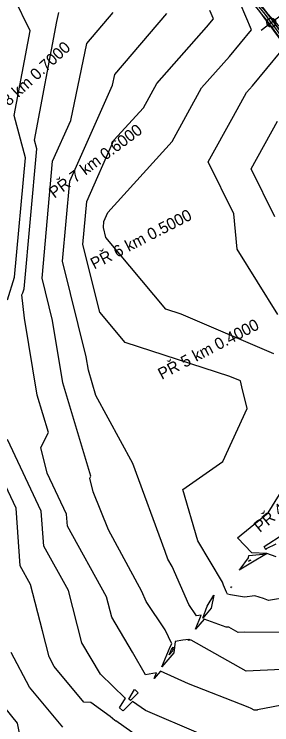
# Model space of a CAD drawing. Extents: x -549394 to -546608, y -1037055 to -1033629.
# Drawn here: x -548203 to -548001, y -1034976 to -1034420 of the extents above; entities that cross this region are included whole.
import ezdxf

# ---------------------------------------------------------------- set-up
doc = ezdxf.new("R2010")
doc.units = 0
for name, color, linetype in [('hlavni_vrst', 7, 'Continuous'), ('norm_vrst', 7, 'Continuous'), ('u_sirka_1_5m', 7, 'Continuous'), ('x_navrh_C21', 7, 'Continuous'), ('x_osa_C21', 7, 'Continuous'), ('x_popis_pricne_rezy_C21', 7, 'Continuous'), ('x_popis_velky_C21', 7, 'Continuous')]:
    doc.layers.add(name, color=color, linetype=linetype)

msp = doc.modelspace()

# ---------------------------------------------------------------- linework, layer by layer
at = {"layer": 'hlavni_vrst'}
for p, q in [((-548146.08, -1034442.45), (-548125.53, -1034418.32)), ((-548158.61, -1034502.63), (-548146.08, -1034442.45)), ((-548172.84, -1034534.63), (-548158.61, -1034502.63)), ((-548017.39, -1034540.43), (-547996.78, -1034503.15)), ((-548181.01, -1034626.04), (-548172.84, -1034534.63)), ((-547998.99, -1034578.18), (-548017.39, -1034540.43)), ((-548172.85, -1034659.09), (-548181.01, -1034626.04)), ((-548164.9, -1034707.86), (-548172.85, -1034659.09)), ((-548142.85, -1034780.89), (-548164.9, -1034707.86)), ((-548143.73, -1034782.59), (-548142.85, -1034780.89)), ((-548140.96, -1034793.3), (-548143.73, -1034782.59)), ((-548129.19, -1034823), (-548140.96, -1034793.3)), ((-548102.99, -1034871.31), (-548129.19, -1034823)), ((-548099.52, -1034879.12), (-548102.99, -1034871.31)), ((-548084.87, -1034901.12), (-548099.52, -1034879.12)), ((-548079.44, -1034912.17), (-548084.87, -1034901.12)), ((-548076.88, -1034910.42), (-548077.94, -1034919.17)), ((-548071.04, -1034909.31), (-548076.88, -1034910.42)), ((-548066.15, -1034908.68), (-548071.04, -1034909.31)), ((-548066.47, -1034909.49), (-548066.15, -1034908.68)), ((-548065.96, -1034908.91), (-548066.47, -1034909.49)), ((-548064.69, -1034909.38), (-548065.96, -1034908.91)), ((-548064.55, -1034909.36), (-548064.69, -1034909.38)), ((-548021.3, -1034933.65), (-548064.55, -1034909.36)), ((-548087.44, -1034930.05), (-548080.86, -1034914.52)), ((-548080.86, -1034914.52), (-548079.44, -1034912.17)), ((-548077.94, -1034919.17), (-548087.44, -1034930.05)), ((-547993.65, -1034932.39), (-548021.3, -1034933.65)), ((-548200.15, -1034974.14), (-548210.1, -1034962.11)), ((-548198.58, -1034982.16), (-548200.15, -1034974.14))]:
    msp.add_line(p, q, dxfattribs=at)
at = {"layer": 'norm_vrst'}
for p, q in [((-548190.3, -1034432.56), (-548227.23, -1034357.2)), ((-548017.25, -1034431.88), (-548026.05, -1034410.86)), ((-548047.04, -1034423.24), (-548049.77, -1034416.71)), ((-548169.38, -1034425.17), (-548167.91, -1034418.13)), ((-548124.25, -1034466.77), (-548083.54, -1034418.98)), ((-548186.88, -1034518.02), (-548169.38, -1034425.17)), ((-548052.38, -1034429.67), (-548047.04, -1034423.24)), ((-548202.78, -1034498.76), (-548190.3, -1034432.56)), ((-548091.3, -1034473.64), (-548052.38, -1034429.67)), ((-548034.46, -1034452.59), (-548017.25, -1034431.88)), ((-548016.54, -1034475.52), (-547994.11, -1034448.52)), ((-548056.24, -1034477.2), (-548034.46, -1034452.59)), ((-548125.98, -1034475.07), (-548124.25, -1034466.77)), ((-548159.45, -1034550.3), (-548125.98, -1034475.07)), ((-548101.78, -1034492.75), (-548091.3, -1034473.64)), ((-548079.18, -1034519.05), (-548056.24, -1034477.2)), ((-548021.17, -1034480.75), (-548016.54, -1034475.52)), ((-548031.4, -1034499.41), (-548021.17, -1034480.75)), ((-548124.79, -1034518.16), (-548101.78, -1034492.75)), ((-548193.98, -1034532.04), (-548202.78, -1034498.76)), ((-548051.05, -1034534.94), (-548031.4, -1034499.41)), ((-548185.07, -1034524.89), (-548186.88, -1034518.02)), ((-548146.06, -1034565.97), (-548124.79, -1034518.16)), ((-548129.58, -1034574.7), (-548079.18, -1034519.05)), ((-548195.18, -1034634.51), (-548185.07, -1034524.89)), ((-548202.58, -1034625.32), (-548193.98, -1034532.04)), ((-548031.16, -1034575.74), (-548051.05, -1034534.94)), ((-548165.04, -1034612.88), (-548159.45, -1034550.3)), ((-548149.08, -1034599.71), (-548146.06, -1034565.97)), ((-548132.68, -1034581.65), (-548129.58, -1034574.7)), ((-548028.57, -1034603.4), (-548031.16, -1034575.74)), ((-548133.11, -1034586.55), (-548132.68, -1034581.65)), ((-548131.21, -1034594.26), (-548133.11, -1034586.55)), ((-548084.19, -1034650.32), (-548131.21, -1034594.26)), ((-548135.97, -1034652.77), (-548149.08, -1034599.71)), ((-547996.51, -1034654.45), (-548028.57, -1034603.4)), ((-548146.55, -1034687.75), (-548165.04, -1034612.88)), ((-548208.07, -1034642.95), (-548202.58, -1034625.32)), ((-548196.89, -1034639.11), (-548196.13, -1034637.57)), ((-548194.75, -1034657.36), (-548196.89, -1034639.11)), ((-548196.13, -1034637.57), (-548195.18, -1034634.51)), ((-548072.27, -1034654.17), (-548084.19, -1034650.32)), ((-548116.13, -1034676.43), (-548135.97, -1034652.77)), ((-547999.8, -1034685.36), (-548072.27, -1034654.17)), ((-548184.93, -1034717.6), (-548194.75, -1034657.36)), ((-548034.09, -1034702.92), (-548116.13, -1034676.43)), ((-548144.86, -1034698.12), (-548146.55, -1034687.75)), ((-548138.9, -1034717.87), (-548144.86, -1034698.12)), ((-548025.76, -1034706.51), (-548034.09, -1034702.92)), ((-548024.71, -1034711.2), (-548025.76, -1034706.51)), ((-548020.75, -1034727.95), (-548024.71, -1034711.2)), ((-548176.09, -1034746.9), (-548184.93, -1034717.6)), ((-548109.97, -1034770.99), (-548138.9, -1034717.87)), ((-548039.64, -1034769.5), (-548020.75, -1034727.95)), ((-548182.14, -1034758.61), (-548176.09, -1034746.9)), ((-548181.64, -1034808.42), (-548207.99, -1034752.34)), ((-548176.94, -1034778.68), (-548182.14, -1034758.61)), ((-548201.42, -1034806.04), (-548221.28, -1034763.77)), ((-548084.86, -1034840.06), (-548109.97, -1034770.99)), ((-548070.96, -1034791.48), (-548039.64, -1034769.5)), ((-548161.86, -1034810.79), (-548176.94, -1034778.68)), ((-548059.11, -1034831.52), (-548070.96, -1034791.48)), ((-548004.18, -1034809.72), (-547995.42, -1034795.27)), ((-548198.21, -1034851.18), (-548201.42, -1034806.04)), ((-548179.7, -1034835.65), (-548181.64, -1034808.42)), ((-548161.19, -1034820.11), (-548161.86, -1034810.79)), ((-548028.31, -1034829.28), (-548004.18, -1034809.72)), ((-548130.56, -1034875.29), (-548161.19, -1034820.11)), ((-548007.41, -1034835.99), (-547991.97, -1034826.01)), ((-548039.89, -1034863.86), (-548059.11, -1034831.52)), ((-548016.86, -1034840.89), (-548028.31, -1034829.28)), ((-548160.33, -1034870.54), (-548179.7, -1034835.65)), ((-548006, -1034838.59), (-548007.41, -1034835.99)), ((-548005.82, -1034837.88), (-548006, -1034838.59)), ((-547998.17, -1034834.14), (-548005.82, -1034837.88)), ((-548082.56, -1034845.87), (-548084.86, -1034840.06)), ((-548026.18, -1034853.86), (-548019.45, -1034844.98)), ((-548019.45, -1034844.98), (-548019.3, -1034843.12)), ((-548019.3, -1034843.12), (-548005.47, -1034841.82)), ((-548005.47, -1034841.82), (-548017.71, -1034849.03)), ((-548005.35, -1034841.47), (-548016.86, -1034840.89)), ((-548005.25, -1034841.66), (-548005.35, -1034841.47)), ((-548005.18, -1034841.41), (-548005.25, -1034841.66)), ((-547997.95, -1034844.08), (-548005.18, -1034841.41)), ((-548079.34, -1034851.8), (-548082.56, -1034845.87)), ((-548017.71, -1034849.03), (-548026.84, -1034854.66)), ((-548018.72, -1034847.22), (-548019.47, -1034847.69)), ((-548019.47, -1034847.69), (-548019.42, -1034847.62)), ((-548019.42, -1034847.62), (-548018.86, -1034846.89)), ((-548018.86, -1034846.89), (-548018.85, -1034846.73)), ((-548018.85, -1034846.73), (-548017.71, -1034846.63)), ((-548017.71, -1034846.63), (-548018.72, -1034847.22)), ((-548190.1, -1034865.79), (-548198.21, -1034851.18)), ((-548066.23, -1034881.33), (-548079.34, -1034851.8)), ((-548026.84, -1034854.66), (-548026.18, -1034853.86)), ((-548180.76, -1034902.12), (-548190.1, -1034865.79)), ((-548039.04, -1034866.27), (-548039.89, -1034863.86)), ((-548036.77, -1034871.74), (-548039.04, -1034866.27)), ((-548149.83, -1034911.36), (-548160.33, -1034870.54)), ((-548035.91, -1034873.34), (-548036.77, -1034871.74)), ((-548032.99, -1034867.74), (-548033.28, -1034867.88)), ((-548033.28, -1034867.88), (-548033.22, -1034867.96)), ((-548033.27, -1034868.41), (-548032.89, -1034867.65)), ((-548033.22, -1034867.96), (-548033.27, -1034868.41)), ((-548032.89, -1034867.65), (-548032.99, -1034867.74)), ((-548126.46, -1034891.22), (-548130.56, -1034875.29)), ((-548051.83, -1034882.77), (-548046.58, -1034874.17)), ((-548046.58, -1034874.17), (-548048.77, -1034884.33)), ((-548033.72, -1034873.9), (-548035.91, -1034873.34)), ((-548022.71, -1034875.76), (-548033.72, -1034873.9)), ((-548014.61, -1034874.54), (-548022.71, -1034875.76)), ((-548007.97, -1034876.79), (-548014.61, -1034874.54)), ((-548003.88, -1034878.17), (-548007.97, -1034876.79)), ((-547982.46, -1034874.58), (-548003.88, -1034878.17)), ((-548060.3, -1034890.23), (-548066.23, -1034881.33)), ((-548055.4, -1034892.04), (-548051.83, -1034882.77)), ((-548048.77, -1034884.33), (-548055.4, -1034892.04)), ((-548110.29, -1034918.6), (-548126.46, -1034891.22)), ((-548060.93, -1034900.77), (-548056.69, -1034889.77)), ((-548054.13, -1034892.86), (-548060.93, -1034900.77)), ((-548056.69, -1034889.77), (-548060.3, -1034890.23)), ((-548036.92, -1034899.22), (-548054.13, -1034892.86)), ((-548035.07, -1034899.04), (-548036.92, -1034899.22)), ((-548027.56, -1034903.25), (-548035.07, -1034899.04)), ((-548175.6, -1034922.33), (-548180.76, -1034902.12)), ((-548022.77, -1034903.03), (-548027.56, -1034903.25)), ((-547988.35, -1034903.27), (-548022.77, -1034903.03)), ((-548135.34, -1034935.88), (-548149.83, -1034911.36)), ((-548081.56, -1034920.82), (-548079.78, -1034916.62)), ((-548079.78, -1034916.62), (-548078.6, -1034914.67)), ((-548078.6, -1034914.67), (-548078.99, -1034917.88)), ((-548190.85, -1034946.02), (-548205.16, -1034918.95)), ((-548171.59, -1034929.93), (-548175.6, -1034922.33)), ((-548100.2, -1034936.38), (-548110.29, -1034918.6)), ((-548078.99, -1034917.88), (-548081.56, -1034920.82)), ((-548148.41, -1034957.93), (-548171.59, -1034929.93)), ((-548088.41, -1034933.65), (-548093.32, -1034939.28)), ((-548066.5, -1034943.54), (-548088.41, -1034933.65)), ((-548115.98, -1034954.78), (-548135.34, -1034935.88)), ((-548091.42, -1034934.79), (-548100.2, -1034936.38)), ((-548093.32, -1034939.28), (-548091.42, -1034934.79)), ((-548019.86, -1034961.81), (-548066.5, -1034943.54)), ((-548164.85, -1034977.44), (-548190.85, -1034946.02)), ((-548113.27, -1034955.43), (-548108.63, -1034947.86)), ((-548105.77, -1034950.4), (-548112, -1034956.5)), ((-548108.63, -1034947.86), (-548108.21, -1034948.2)), ((-548108.21, -1034948.2), (-548105.77, -1034950.4)), ((-548120.5, -1034962.22), (-548115.91, -1034954.73)), ((-548115.91, -1034954.73), (-548115.98, -1034954.78)), ((-548112.22, -1034956.37), (-548113.27, -1034955.43)), ((-547970.95, -1034956.03), (-548012.58, -1034963.69)), ((-548142.91, -1034958.09), (-548148.41, -1034957.93)), ((-548127.88, -1034969.1), (-548142.91, -1034958.09)), ((-548110.32, -1034957.28), (-548117.74, -1034964.56)), ((-548112, -1034956.5), (-548112.22, -1034956.37)), ((-548100.16, -1034964.38), (-548110.32, -1034957.28)), ((-548017.41, -1034962.72), (-548019.86, -1034961.81)), ((-548118.22, -1034964.27), (-548120.5, -1034962.22)), ((-548117.74, -1034964.56), (-548118.22, -1034964.27)), ((-548058.63, -1034981.96), (-548100.16, -1034964.38)), ((-548015.03, -1034964.05), (-548017.41, -1034962.72)), ((-548012.91, -1034963.95), (-548015.03, -1034964.05)), ((-548012.58, -1034963.69), (-548012.91, -1034963.95)), ((-548127.69, -1034968.94), (-548127.88, -1034969.1)), ((-548127.88, -1034969.1), (-548127.88, -1034969.1)), ((-548127.88, -1034969.1), (-548127.88, -1034969.1)), ((-548127.88, -1034969.1), (-548127.88, -1034969.1)), ((-548127.74, -1034969.01), (-548127.69, -1034968.94)), ((-548124.22, -1034972.17), (-548127.74, -1034969.01)), ((-548124.22, -1034972.17), (-548124.22, -1034972.17)), ((-548124.22, -1034972.17), (-548124.22, -1034972.17)), ((-548124.22, -1034972.17), (-548124.22, -1034972.17)), ((-548123.48, -1034972.61), (-548124.22, -1034972.17)), ((-548123.33, -1034972.47), (-548123.48, -1034972.61)), ((-548088.99, -1034996.46), (-548123.33, -1034972.47))]:
    msp.add_line(p, q, dxfattribs=at)
at = {"layer": 'u_sirka_1_5m'}
msp.add_circle((-548001.76, -1034426.1), 3.5, dxfattribs=at)
at = {"layer": 'x_navrh_C21'}
for radius in [498, 502]:
    msp.add_arc((-548402.5, -1034725.11), radius, 27.187, 42.6945, dxfattribs=at)
at = {"layer": 'x_osa_C21'}
msp.add_lwpolyline([(-547988.85, -1034436.1), (-548081.2, -1034336.01), (-548179.05, -1034250.71), (-548179.05, -1034250.71), (-548370.93, -1034073.7), (-548415.61, -1034028.48), (-548434.5, -1034013.39)], dxfattribs=at)
msp.add_arc((-548402.5, -1034725.11), 500, 27.187, 42.6945, dxfattribs=at)
at = {"layer": 'x_popis_pricne_rezy_C21'}
msp.add_lwpolyline([(-548009.78, -1034432.08), (-548001.76, -1034426.1), (-547993.75, -1034420.12)], dxfattribs=at)
at = {"layer": 'x_popis_velky_C21'}
for radius in [498.25, 501.75]:
    msp.add_arc((-548402.5, -1034725.11), radius, 27.187, 42.6945, dxfattribs=at)

# ---------------------------------------------------------------- texts
at = {"layer": 'x_popis_pricne_rezy_C21'}
for s, rotation, p in [('PŘ 8 km 0.7000', 42.6945, (-548221.92, -1034505.62)), ('PŘ 7 km 0.6000', 36.728, (-548171.42, -1034563.99)), ('PŘ 6 km 0.5000', 27.187, (-548140.27, -1034619.41)), ('PŘ 5 km 0.4000', 27.5618, (-548087.44, -1034705.69)), ('PŘ 4 km 0.3000', 39.4445, (-548010.7, -1034825.52))]:
    msp.add_text(s, height=9.0627, rotation=rotation, dxfattribs=at).set_placement(p)

doc.saveas('drawing.dxf')
